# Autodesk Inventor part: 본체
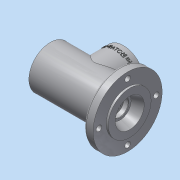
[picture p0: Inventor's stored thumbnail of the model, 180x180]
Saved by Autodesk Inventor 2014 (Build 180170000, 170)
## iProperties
Created: 2016-08
Part Number: 본체
Material: 알루미늄 6061
Document SubType Name: Modeling
Designer: 406-9
Density: 2.71 g/cm^3
Appearance: 알루미늄 - 평지
Mass: 787.986 g
Surface Area: 627.587 cm^2
Volume: 290.77 cm^3
Author: 406-9
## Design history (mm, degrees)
sketch "스케치1"
  geometry: L1 (-57.5, 0)-(57.5, 0); L2 (-57.5, 0)-(-57.5, 31); L3 (-57.5, 31)-(41.5, 31); L4 (41.5, 31)-(41.5, 50); L5 (41.5, 50)-(54.5, 50); L6 (54.5, 50)-(54.5, 31); L7 (54.5, 31)-(57.5, 31); L8 (57.5, 31)-(57.5, 0); 2 further points
  constraints: 16 end point, 4 parallel, 2 perpendicular, 1 coincident, 1 collinear, 1 horizontal, 1 midpoint
  dimensions: "d0" = 115 distance of L1.start L1.end; "d1" = 62 diameter of L3 L1; "d2" = 62 diameter of L7 L1; "d3" = 3 distance of L6.end L7.end; "d4" = 13 distance of L4.end L5.end; "d5" = 100 diameter of L5 L1
revolve "회전1" sketch "스케치1" stored, may be unused: angle "d6" = 90 deg
sketch "스케치2"
  geometry: A1 r 41.5 centre (0, 0) between (0, 41.5) and (0, -41.5); 3 further points
  constraints: 4 point on circle, 2 horizontal alignment, 2 vertical alignment, 1 centre point, 1 coincident
  dimensions: "d7" = 83 diameter of A1
hole "구멍1" sketch "스케치2" at (0, 41.5), (0, -41.5), (-41.5, 0), (41.5, 0) diameter "d8" = 8; stored, may be unused: countersink angle "d12" = 90 deg, drill point angle "d14" = 118 deg; dims "d9" = 6, "d10" = 4, "d11" = 2, "d13" = 8
sketch "스케치4"
  geometry: 2 further points
  constraints: 1 coincident
hole "구멍2" sketch "스케치4" at (0, 0) diameter "d61" = 40.376; stored, may be unused: countersink angle "d65" = 90 deg, drill point angle "d67" = 0 deg; dims "d62" = 9, "d63" = 4, "d64" = 2, "d66" = 9
sketch "스케치5"
  geometry: C1 r 24 at (0, 0); 1 further point
  constraints: 1 centre point, 1 coincident
  dimensions: "d68" = 48 diameter of C1
extrude "돌출1" cut sketch "스케치5" distance "d69" = 3; taper "d70" = 0 deg
sketch "스케치6"
  geometry: C1 r 20 at (0, 0); 1 further point
  constraints: 1 centre point, 1 coincident
  dimensions: "d71" = 40 diameter of C1
extrude "돌출2" cut sketch "스케치6" distance "d72" = 9; taper "d73" = 0 deg
sketch "스케치9"
  geometry: C1 r 17.5 at (0, 0); 1 further point
  constraints: 1 centre point, 1 coincident
  dimensions: "d77" = 35 diameter of C1
extrude "돌출4" cut sketch "스케치9" distance "d78" = 3.25; taper "d79" = 0 deg
sketch "스케치10"
  geometry: C1 r 18.5 at (0, 0); 1 further point
  constraints: 1 centre point, 1 coincident
  dimensions: "d80" = 37 diameter of C1
extrude "돌출5" cut sketch "스케치10" distance "d81" = 1.75; taper "d82" = 0 deg
sketch "스케치11"
  geometry: L1 (-31.5, -18.5)-(-31.5, 18.5) reference; L2 (-31.5, 0)-(57.5, 0); L3 (-31.5, 0.096)-(-31.5, 17.5); L4 (57.5, 21)-(43.5, 16); L5 (43.5, 16)-(43.5, 12.904); L6 (42.8, 12.5)-(36.2, 12.5); L7 (33.5, 16.5)-(28.5, 16.5); L8 (28.5, 16.5)-(28.5, 17.5); L9 (57.5, -31)-(57.5, 31) reference; L10 (42.8, 12.5)-(43.5, 12.904); L11 (36.2, 12.5)-(36.2, 10); L12 (33.5, 16.5)-(33.5, 10); L13 (33.5, 10)-(36.2, 10); L14 (28.5, 16.5)-(28.5, 0); L15 (57.5, 21)-(57.5, 0); 1 further point
  constraints: 26 end point, 4 perpendicular, 4 point on line, 3 parallel, 1 collinear, 1 horizontal, 1 midpoint
  dimensions: "d83" = 14 horizontal distance of L4.start L4.end; "d85" = 5 distance of L7.start L7.end; "d86" = 0.7 horizontal distance of L5.end L6.start; "d87" = 30 deg angle of L6 L10; "d90" = 2.7 distance of L12.end L11.end; "d91" = 42 diameter of L4.start L2; "d92" = 32 diameter of L4.end L2; "d93" = 25 diameter of L6 L2; "d94" = 20 diameter of L13 L2; "d95" = 33 diameter of L7 L2; "d100" = 7.3 horizontal distance of L5.end L6.end
revolve "회전2" sketch "스케치11" stored, may be unused: angle "d99" = 90 deg
sketch "스케치12"
  geometry: L1 (-31.5, -18.5)-(-31.5, 18.5) reference; L2 (-31.5, 0)-(28.5, 0); L3 (-31.5, 17.5)-(-17.5, 17.5); L4 (-17.5, 17.5)-(-17.5, 26); L5 (-17.5, 26)-(14.5, 26); L6 (14.5, 26)-(14.5, 17.5); L7 (14.5, 17.5)-(28.5, 17.5); L8 (28.5, 16.5)-(28.5, -16.5) reference; L9 (28.5, 17.5)-(28.5, 0); L10 (-31.5, 17.5)-(-31.5, 0); 1 further point
  constraints: 16 end point, 4 perpendicular, 2 collinear, 2 point on line, 1 horizontal, 1 midpoint, 1 parallel
  dimensions: "d101" = 60 distance of L2.start L2.end; "d102" = 35 diameter of L3 L2; "d103" = 52 diameter of L5 L2; "d104" = 35 diameter of L7 L2
revolve "회전3" sketch "스케치12" stored, may be unused: angle "d105" = 90 deg
node "작업 평면1"
sketch "스케치13"
  geometry: L1 (57.5, 31)-(57.5, -31) reference; C1 r 30 at (1.5, 0); 1 further point
  constraints: 1 centre point, 1 horizontal alignment
  dimensions: "d107" = 60 diameter of C1; "d108" = 56 distance from line of L1 C1.centre
extrude "돌출6" join sketch "스케치13" stored distance "d109" = 1.75; taper "d110" = 0 deg
sketch "스케치14"
  geometry: L1 (56, -50)-(56, 50) reference; L2 (-56, -31)-(-56, 31) reference; C1 r 19 at (0, 0); 1 further point
  constraints: 1 centre point, 1 horizontal alignment
  dimensions: "d111" = 38 diameter of C1; "d113" = 56 distance from line of C1.centre L2
extrude "돌출7" cut sketch "스케치14" stored distance "d114" = 1.75; taper "d115" = 0 deg
sketch "스케치15"
  geometry: C1 r 30 at (0, 0) reference; A1 r 24 centre (0, 0) between (-24, 0) and (24, 0); 3 further points
  constraints: 4 point on circle, 2 horizontal alignment, 2 vertical alignment, 1 centre point, 1 coincident
  dimensions: "d116" = 48 diameter of A1
hole "구멍3" sketch "스케치15" at (-24, 0), (24, 0), (0, 24), (0, -24) diameter "d117" = 3.242; stored, may be unused: countersink angle "d121" = 90 deg, drill point angle "d123" = 0 deg; dims "d118" = 8, "d119" = 4, "d120" = 2, "d122" = 10
node "작업 평면2"
sketch "스케치16"
  geometry: L1 (-57.5, -31)-(-57.5, 31) reference; L2 (-31.5, 50)-(28.5, 50) reference; 2 further points
  constraints: 1 other
  dimensions: "d125" = 56 distance from line of L1 point (-1.5, 40); "d126" = 10 distance from line of point (-1.5, 40) L2
feature "엠보싱1" sketch "스케치16" dims "d64" = 2, "d127" = 0.5, "d128" = 0
chamfer "모따기1" distance "d129" = 1; stored, may be unused: second distance "d130" = 2, angle "d131" = 45 deg
fillet "모깎기1" dims "d132" = 0.3
fillet "모깎기2" dims "d133" = 3
fillet "모깎기3" dims "d134" = 0.3
node "솔리드1"
